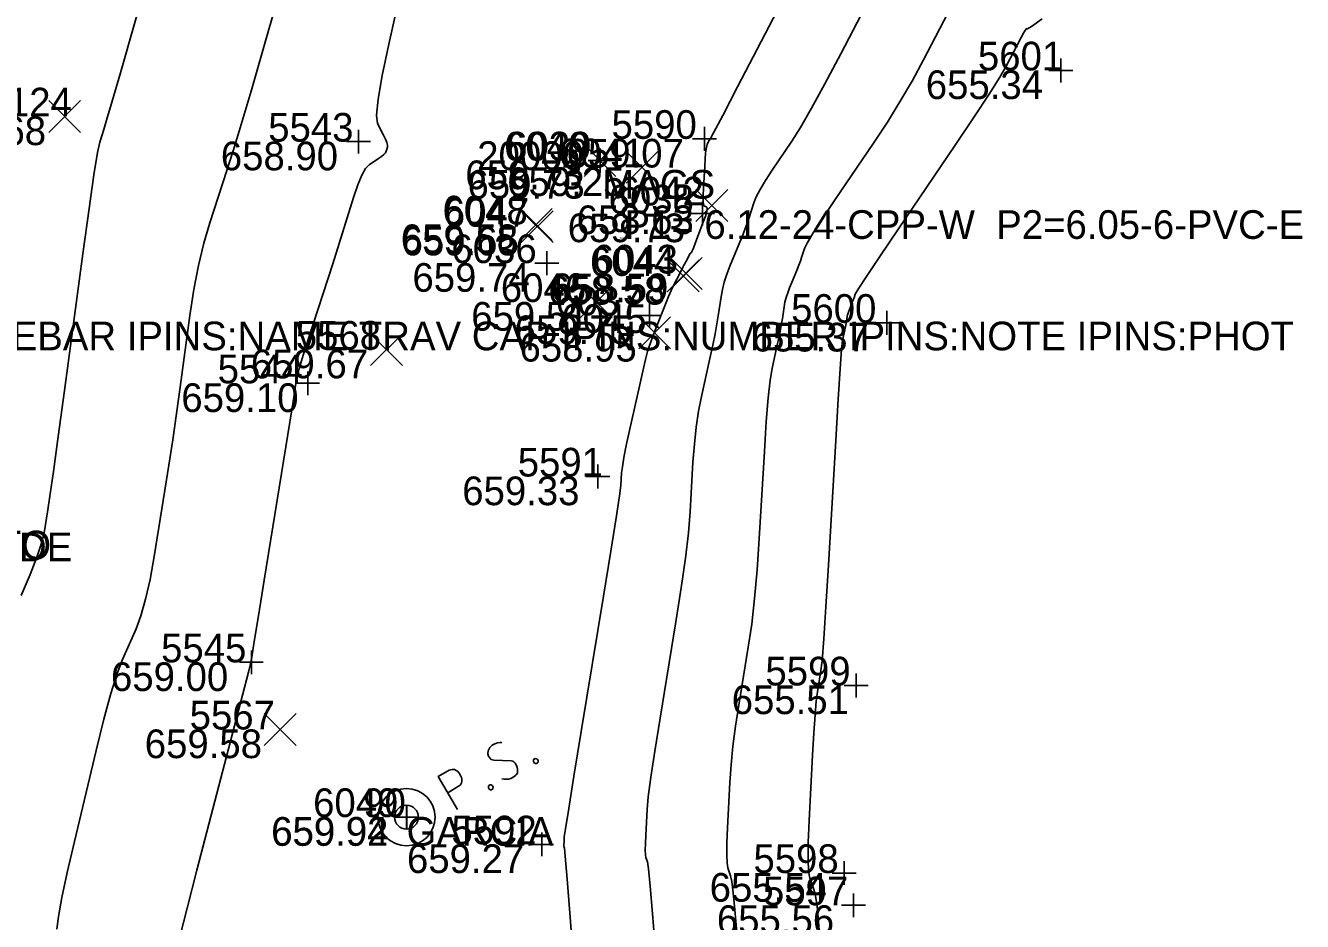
# Model space of a CAD drawing. Extents: x 2129350 to 2137777, y 657588 to 659885.
# Drawn here: x 2132984.1 to 2133037.5, y 658421.4 to 658458.9 of the extents above; entities that cross this region are included whole.
import ezdxf

# ---------------------------------------------------------------- set-up
doc = ezdxf.new("R2010")
doc.units = 0
for name, color, linetype in [('DT_X_Contour_Minor', 7, 'Continuous'), ('SV_P_Mon_Cells_Set', 7, 'Continuous'), ('SV_X_Random_Point', 7, 'Continuous'), ('SV_X_Shot_Marker', 7, 'Continuous'), ('SV_X_Text_Comment', 7, 'Continuous'), ('SV_X_Text_Description', 7, 'Continuous'), ('SV_X_Text_Elevation', 7, 'Continuous'), ('SV_X_Text_Name', 7, 'Continuous')]:
    doc.layers.add(name, color=color, linetype=linetype)

msp = doc.modelspace()

# ---------------------------------------------------------------- linework, layer by layer
at = {"layer": 'DT_X_Contour_Minor'}
for points in [[(2132989.848, 658463.205), (2132988.036, 658456.873), (2132987.693, 658455.686), (2132987.462, 658454.895), (2132987.342, 658454.5), (2132987.171, 658453.973), (2132987.078, 658453.532), (2132986.93, 658452.605), (2132986.725, 658451.191), (2132986.464, 658449.291), (2132985.693, 658443.576), (2132985.433, 658441.656), (2132985.23, 658440.183), (2132985.085, 658439.155), (2132984.998, 658438.574), (2132984.843, 658437.619), (2132984.74, 658437.186), (2132984.545, 658436.604), (2132984.259, 658435.873), (2132983.882, 658434.993)], [(2133017.349, 658462.959), (2133013.87, 658456.279), (2133013.249, 658455.089), (2133012.869, 658454.364), (2133012.728, 658454.102), (2133012.674, 658454.022), (2133012.655, 658453.99), (2133012.636, 658453.955), (2133012.62, 658453.915), (2133012.605, 658453.872), (2133012.566, 658453.752), (2133012.551, 658453.67), (2133012.534, 658453.511), (2133012.516, 658453.277), (2133012.497, 658452.967), (2133012.443, 658452.039), (2133012.43, 658451.732), (2133012.432, 658451.506), (2133012.449, 658451.363), (2133012.48, 658451.302), (2133012.584, 658451.248), (2133012.605, 658451.196), (2133012.59, 658451.08), (2133012.539, 658450.9), (2133012.452, 658450.657), (2133012.172, 658449.922), (2133012.079, 658449.68), (2133012.01, 658449.505), (2133011.964, 658449.398), (2133011.941, 658449.357), (2133011.913, 658449.339), (2133011.888, 658449.305), (2133011.836, 658449.213), (2133011.757, 658449.065), (2133011.65, 658448.861), (2133011.328, 658448.241), (2133011.209, 658448.005), (2133011.094, 658447.761), (2133010.984, 658447.511), (2133010.877, 658447.254), (2133010.598, 658446.557), (2133010.501, 658446.312), (2133010.417, 658446.099), (2133010.349, 658445.918), (2133010.294, 658445.769), (2133010.167, 658445.414), (2133010.106, 658445.21), (2133010.019, 658444.867), (2133009.904, 658444.382), (2133009.763, 658443.758), (2133009.351, 658441.905), (2133009.215, 658441.273), (2133009.114, 658440.766), (2133009.049, 658440.383), (2133009.02, 658440.125), (2133008.989, 658439.604), (2133008.935, 658439.168), (2133008.797, 658438.25), (2133008.573, 658436.849), (2133008.265, 658434.967), (2133007.33, 658429.306), (2133007.023, 658427.438), (2133006.802, 658426.079), (2133006.668, 658425.23), (2133006.62, 658424.89), (2133006.608, 658424.661), (2133006.605, 658424.585), (2133006.604, 658424.526), (2133006.606, 658424.484), (2133006.61, 658424.46), (2133006.624, 658424.42), (2133006.654, 658424.089), (2133006.733, 658423.125), (2133006.861, 658421.528), (2133007.038, 658419.298)], [(2133000.154, 658462.007), (2132999.27, 658458.075), (2132998.992, 658456.762), (2132998.821, 658455.771), (2132998.757, 658455.103), (2132998.8, 658454.757), (2132999.056, 658454.264), (2132999.138, 658454.095), (2132999.191, 658453.955), (2132999.216, 658453.846), (2132999.212, 658453.767), (2132999.162, 658453.597), (2132999.128, 658453.529), (2132999.062, 658453.454), (2132998.965, 658453.371), (2132998.836, 658453.28), (2132998.449, 658453.027), (2132998.299, 658452.87), (2132998.14, 658452.589), (2132997.97, 658452.182), (2132997.791, 658451.652), (2132996.93, 658448.884), (2132995.896, 658445.705), (2132995.7, 658445.096), (2132995.556, 658444.632), (2132995.464, 658444.312), (2132995.424, 658444.136), (2132995.387, 658443.862), (2132995.34, 658443.557), (2132995.227, 658442.848), (2132995.048, 658441.737), (2132994.06, 658435.642), (2132993.816, 658434.139), (2132993.641, 658433.065), (2132993.536, 658432.42), (2132993.501, 658432.204), (2132993.496, 658432.189), (2132993.49, 658432.165), (2132993.481, 658432.126), (2132993.468, 658432.072), (2132993.399, 658431.787), (2132991.243, 658423.501), (2132990.832, 658421.914), (2132990.522, 658420.702)], [(2133020.094, 658461.324), (2133018.192, 658457.67), (2133017.529, 658456.414), (2133016.967, 658455.386), (2133016.506, 658454.586), (2133016.145, 658454.015), (2133015.318, 658452.794), (2133015.038, 658452.365), (2133014.817, 658451.994), (2133014.655, 658451.681), (2133014.553, 658451.426), (2133014.359, 658450.821), (2133014.278, 658450.58), (2133014.179, 658450.311), (2133014.063, 658450.012), (2133013.93, 658449.685), (2133013.551, 658448.774), (2133013.421, 658448.438), (2133013.316, 658448.112), (2133013.236, 658447.798), (2133013.18, 658447.493), (2133013.064, 658446.696), (2133013.01, 658446.36), (2133012.933, 658445.951), (2133012.834, 658445.467), (2133012.713, 658444.911), (2133012.361, 658443.328), (2133012.24, 658442.711), (2133012.141, 658442.047), (2133012.063, 658441.335), (2133012.006, 658440.576), (2133011.885, 658438.49), (2133011.814, 658437.617), (2133011.692, 658436.56), (2133011.518, 658435.32), (2133011.293, 658433.897), (2133010.626, 658429.858), (2133010.405, 658428.482), (2133010.241, 658427.386), (2133010.134, 658426.569), (2133010.085, 658426.031), (2133010.029, 658424.967), (2133010.014, 658424.609), (2133010.011, 658424.334), (2133010.018, 658424.141), (2133010.037, 658424.029), (2133010.102, 658423.843), (2133010.142, 658423.556), (2133010.211, 658422.835), (2133010.309, 658421.681), (2133010.438, 658420.092)], [(2133022.84, 658459.689), (2133021.653, 658457.409), (2133021.188, 658456.55), (2133020.685, 658455.683), (2133020.143, 658454.809), (2133019.562, 658453.927), (2133017.963, 658451.566), (2133017.432, 658450.774), (2133017.04, 658450.168), (2133016.787, 658449.748), (2133016.673, 658449.515), (2133016.553, 658449.141), (2133016.502, 658448.991), (2133016.441, 658448.824), (2133016.369, 658448.64), (2133016.287, 658448.437), (2133016.053, 658447.873), (2133015.972, 658447.665), (2133015.907, 658447.463), (2133015.857, 658447.268), (2133015.823, 658447.08), (2133015.751, 658446.586), (2133015.717, 658446.378), (2133015.67, 658446.125), (2133015.609, 658445.826), (2133015.534, 658445.481), (2133015.316, 658444.501), (2133015.234, 658444.008), (2133015.153, 658443.265), (2133015.073, 658442.272), (2133014.993, 658441.028), (2133014.781, 658437.377), (2133014.692, 658436.065), (2133014.586, 658434.87), (2133014.463, 658433.79), (2133014.322, 658432.826), (2133013.923, 658430.409), (2133013.787, 658429.527), (2133013.68, 658428.693), (2133013.6, 658427.908), (2133013.549, 658427.172), (2133013.451, 658425.273), (2133013.424, 658424.634), (2133013.417, 658424.142), (2133013.431, 658423.797), (2133013.465, 658423.598), (2133013.581, 658423.265), (2133013.63, 658423.023), (2133013.689, 658422.545), (2133013.758, 658421.833), (2133013.838, 658420.886)], [(2132994.424, 658459.269), (2132994.148, 658458.348), (2132993.505, 658456.103), (2132993.261, 658455.264), (2132993.011, 658454.43), (2132992.754, 658453.603), (2132992.49, 658452.781), (2132991.78, 658450.598), (2132991.528, 658449.741), (2132991.305, 658448.808), (2132991.11, 658447.799), (2132990.944, 658446.714), (2132990.54, 658443.719), (2132990.387, 658442.607), (2132990.229, 658441.516), (2132990.067, 658440.446), (2132989.9, 658439.398), (2132989.452, 658436.63), (2132989.278, 658435.663), (2132989.093, 658434.835), (2132988.898, 658434.147), (2132988.691, 658433.598), (2132988.127, 658432.322), (2132987.899, 658431.725), (2132987.639, 658430.89), (2132987.346, 658429.818), (2132987.021, 658428.507), (2132986.111, 658424.696), (2132985.81, 658423.396), (2132985.587, 658422.351), (2132985.444, 658421.563), (2132985.379, 658421.032)], [(2133026.629, 658459.138), (2133026.172, 658458.816), (2133026.009, 658458.712), (2133025.97, 658458.725), (2133025.935, 658458.687), (2133025.859, 658458.563), (2133025.743, 658458.352), (2133025.586, 658458.055), (2133025.114, 658457.147), (2133024.847, 658456.685), (2133024.403, 658455.98), (2133023.78, 658455.032), (2133022.98, 658453.84), (2133020.607, 658450.338), (2133019.826, 658449.183), (2133019.264, 658448.342), (2133018.919, 658447.816), (2133018.793, 658447.604), (2133018.747, 658447.46), (2133018.727, 658447.403), (2133018.676, 658447.267), (2133018.644, 658447.189), (2133018.554, 658446.972), (2133018.523, 658446.892), (2133018.498, 658446.814), (2133018.479, 658446.739), (2133018.466, 658446.667), (2133018.438, 658446.477), (2133018.425, 658446.397), (2133018.407, 658446.299), (2133018.383, 658446.184), (2133018.354, 658446.051), (2133018.27, 658445.674), (2133018.229, 658445.305), (2133018.166, 658444.484), (2133018.083, 658443.208), (2133017.98, 658441.479), (2133017.676, 658436.263), (2133017.571, 658434.514), (2133017.481, 658433.18), (2133017.407, 658432.26), (2133017.35, 658431.755), (2133017.219, 658430.96), (2133017.169, 658430.571), (2133017.118, 658430), (2133017.067, 658429.247), (2133017.014, 658428.313), (2133016.872, 658425.578), (2133016.834, 658424.659), (2133016.824, 658423.95), (2133016.843, 658423.453), (2133016.892, 658423.168), (2133017.06, 658422.688), (2133017.118, 658422.49), (2133017.167, 658422.256), (2133017.207, 658421.986), (2133017.237, 658421.68), (2133017.306, 658420.817)]]:
    msp.add_lwpolyline(points, dxfattribs=at)
at = {"layer": 'SV_P_Mon_Cells_Set'}
for points in [[(2133004.004, 658428.832), (2133003.972, 658428.843), (2133003.931, 658428.848), (2133003.826, 658428.831), (2133003.708, 658428.792), (2133003.632, 658428.747), (2133003.604, 658428.731), (2133003.499, 658428.626), (2133003.432, 658428.5), (2133003.416, 658428.374), (2133003.448, 658428.275), (2133003.486, 658428.21), (2133003.555, 658428.134), (2133003.676, 658428.102), (2133004.39, 658428.08), (2133004.463, 658428.064), (2133004.507, 658428.032), (2133004.564, 658427.978), (2133004.602, 658427.912), (2133004.631, 658427.842), (2133004.647, 658427.792), (2133004.659, 658427.727), (2133004.666, 658427.672), (2133004.665, 658427.628), (2133004.656, 658427.579), (2133004.64, 658427.541), (2133004.615, 658427.497), (2133004.592, 658427.469), (2133004.513, 658427.408), (2133004.379, 658427.331), (2133004.281, 658427.303), (2133004.113, 658427.307), (2133003.999, 658427.328)], [(2133005.349, 658428.142), (2133005.396, 658428.17), (2133005.437, 658428.165), (2133005.491, 658428.138), (2133005.523, 658428.083), (2133005.52, 658428.023), (2133005.504, 658427.985), (2133005.456, 658427.957), (2133005.415, 658427.962), (2133005.361, 658427.989), (2133005.329, 658428.044), (2133005.333, 658428.104), (2133005.349, 658428.142)], [(2133002.15, 658426.034), (2133001.345, 658427.417), (2133001.803, 658427.683), (2133001.857, 658427.7), (2133001.936, 658427.717), (2133001.977, 658427.712), (2133002.019, 658427.707), (2133002.088, 658427.674), (2133002.149, 658427.637), (2133002.218, 658427.561), (2133002.294, 658427.43), (2133002.31, 658427.381), (2133002.329, 658427.304), (2133002.335, 658427.206), (2133002.316, 658427.151), (2133002.3, 658427.113), (2133002.265, 658427.063), (2133002.195, 658427.008), (2133001.738, 658426.742)], [(2133003.462, 658427.045), (2133003.509, 658427.073), (2133003.551, 658427.068), (2133003.605, 658427.041), (2133003.636, 658426.986), (2133003.633, 658426.926), (2133003.617, 658426.888), (2133003.57, 658426.86), (2133003.528, 658426.865), (2133003.474, 658426.892), (2133003.443, 658426.946), (2133003.446, 658427.007), (2133003.462, 658427.045)]]:
    msp.add_lwpolyline(points, dxfattribs=at)
for radius in [1.2, 0.5]:
    msp.add_circle((2133000.015, 658425.718), radius, dxfattribs=at)
at = {"layer": 'SV_X_Random_Point'}
for p, q in [((2132985.038, 658454.378), (2132986.372, 658455.713)), ((2132985.038, 658455.713), (2132986.372, 658454.378)), ((2133007.448, 658452.532), (2133008.782, 658453.867)), ((2133007.448, 658453.867), (2133008.782, 658452.532)), ((2133009.202, 658452.247), (2133010.536, 658453.581)), ((2133009.202, 658453.581), (2133010.536, 658452.247)), ((2133012.125, 658450.654), (2133013.459, 658451.988)), ((2133012.125, 658451.988), (2133013.459, 658450.654)), ((2133004.775, 658449.858), (2133006.109, 658451.193)), ((2133004.775, 658451.193), (2133006.109, 658449.858)), ((2133004.82, 658449.764), (2133006.154, 658451.098)), ((2133004.82, 658451.098), (2133006.154, 658449.764)), ((2133010.929, 658447.703), (2133012.263, 658449.039)), ((2133010.929, 658449.039), (2133012.263, 658447.703)), ((2133011.05, 658447.804), (2133012.384, 658449.139)), ((2133011.05, 658449.139), (2133012.384, 658447.804)), ((2133007.282, 658446.612), (2133008.616, 658447.948)), ((2133007.282, 658447.948), (2133008.616, 658446.612)), ((2133009.737, 658445.318), (2133011.071, 658446.654)), ((2133009.737, 658446.654), (2133011.071, 658445.318)), ((2132998.509, 658444.617), (2132999.843, 658445.953)), ((2132998.509, 658445.953), (2132999.843, 658444.617)), ((2132994.058, 658428.72), (2132995.392, 658430.054)), ((2132994.058, 658430.054), (2132995.392, 658428.72))]:
    msp.add_line(p, q, dxfattribs=at)
at = {"layer": 'SV_X_Shot_Marker'}
for p, q in [((2133027.401, 658457.474), (2133027.401, 658456.474)), ((2133026.901, 658456.974), (2133027.901, 658456.974)), ((2133027.401, 658456.974), (2133027.401, 658456.974)), ((2132998.004, 658454.492), (2132998.004, 658453.492)), ((2133012.489, 658454.608), (2133012.489, 658453.608)), ((2132997.504, 658453.992), (2132998.504, 658453.992)), ((2132998.004, 658453.992), (2132998.004, 658453.992)), ((2133011.989, 658454.108), (2133012.989, 658454.108)), ((2133012.489, 658454.108), (2133012.489, 658454.108)), ((2133008.116, 658453.704), (2133008.116, 658452.704)), ((2133007.616, 658453.204), (2133008.616, 658453.204)), ((2133008.116, 658453.204), (2133008.116, 658453.204)), ((2133012.404, 658451.484), (2133012.404, 658450.484)), ((2133011.904, 658450.984), (2133012.904, 658450.984)), ((2133012.404, 658450.984), (2133012.404, 658450.984)), ((2133005.892, 658449.408), (2133005.892, 658448.408)), ((2133005.392, 658448.908), (2133006.392, 658448.908)), ((2133005.892, 658448.908), (2133005.892, 658448.908)), ((2133010.18, 658447.217), (2133010.18, 658446.217)), ((2133020.12, 658446.908), (2133020.12, 658445.908)), ((2133009.68, 658446.717), (2133010.68, 658446.717)), ((2133010.18, 658446.717), (2133010.18, 658446.717)), ((2133019.62, 658446.408), (2133020.62, 658446.408)), ((2133020.12, 658446.408), (2133020.12, 658446.408)), ((2132995.877, 658444.376), (2132995.877, 658443.376)), ((2132995.377, 658443.876), (2132996.377, 658443.876)), ((2132995.877, 658443.876), (2132995.877, 658443.876)), ((2133008.025, 658440.475), (2133008.025, 658439.475)), ((2133007.525, 658439.975), (2133008.525, 658439.975)), ((2133008.025, 658439.975), (2133008.025, 658439.975)), ((2132993.52, 658432.698), (2132993.52, 658431.698)), ((2132993.02, 658432.198), (2132994.02, 658432.198)), ((2132993.52, 658432.198), (2132993.52, 658432.198)), ((2133018.834, 658431.73), (2133018.834, 658430.73)), ((2133018.334, 658431.23), (2133019.334, 658431.23)), ((2133018.834, 658431.23), (2133018.834, 658431.23)), ((2133000.015, 658426.218), (2133000.015, 658425.218)), ((2133000.025, 658426.222), (2133000.025, 658425.222)), ((2132999.515, 658425.718), (2133000.515, 658425.718)), ((2132999.525, 658425.722), (2133000.525, 658425.722)), ((2133000.015, 658425.718), (2133000.015, 658425.718)), ((2133000.025, 658425.722), (2133000.025, 658425.722)), ((2133005.674, 658425.078), (2133005.674, 658424.078)), ((2133005.174, 658424.578), (2133006.174, 658424.578)), ((2133005.674, 658424.578), (2133005.674, 658424.578)), ((2133018.335, 658423.879), (2133018.335, 658422.879)), ((2133017.835, 658423.379), (2133018.835, 658423.379)), ((2133018.335, 658423.379), (2133018.335, 658423.379)), ((2133018.723, 658422.527), (2133018.723, 658421.527)), ((2133018.223, 658422.027), (2133019.223, 658422.027)), ((2133018.723, 658422.027), (2133018.723, 658422.027))]:
    msp.add_line(p, q, dxfattribs=at)

# ---------------------------------------------------------------- texts
at = {"layer": 'SV_X_Text_Comment'}
for s, p in [('MAGS', (2133008.208, 658451.606)), ('IPINS:SIZE 5/8 REBAR IPINS:NAME TRAV CAP IPINS:NUMBER IPINS:NOTE IPINS:PHOT', (2132971.002, 658445.258)), ('T:TYPE MAPLE T:PHOTO', (2132966.055, 658436.508)), ('BLAZED TREE EAST SIDE', (2132966.226, 658436.426)), ('GARCIA', (2133000.015, 658424.518))]:
    msp.add_text(s, height=1.2, dxfattribs=at).set_placement(p)
at = {"layer": 'SV_X_Text_Description'}
msp.add_text('P1= 6.12-24-CPP-W  P2=6.05-6-PVC-E', height=1.2, dxfattribs=at).set_placement((2133009.137, 658449.921))
at = {"layer": 'SV_X_Text_Elevation'}
for s, height, p in [('655.34', 1.2, (2133021.751, 658455.774)), ('656.68', 1.2, (2132980.017, 658453.846)), ('658.90', 1.2, (2132992.241, 658452.792)), ('659.07', 1.2, (2133006.716, 658452.908)), ('659.73', 1.2, (2133002.474, 658452)), ('659.73', 1.2, (2133002.475, 658452.004)), ('659.73', 1.2, (2133002.567, 658451.606)), ('659.25', 1.2, (2133004.228, 658451.714)), ('658.63', 1.2, (2133007.133, 658450.121)), ('659.73', 1.2, (2133006.763, 658449.784)), ('659.58', 1.2, (2132999.773, 658449.326)), ('659.65', 1.2, (2132999.809, 658449.231)), ('659.71', 0.06, (2133008.878, 658449.861)), ('659.74', 1.2, (2133000.261, 658447.708)), ('658.59', 1.2, (2133006.067, 658447.272)), ('658.58', 1.2, (2133005.946, 658447.171)), ('659.51', 1.2, (2133002.723, 658446.08)), ('659.75', 1.2, (2133004.539, 658445.517)), ('655.37', 1.2, (2133014.461, 658445.208)), ('658.95', 1.2, (2133004.745, 658444.786)), ('659.67', 1.2, (2132993.498, 658444.085)), ('659.10', 1.2, (2132990.587, 658442.676)), ('659.33', 1.2, (2133002.347, 658438.775)), ('659.00', 1.2, (2132987.643, 658430.998)), ('655.51', 1.2, (2133013.627, 658430.03)), ('659.58', 1.2, (2132989.056, 658428.187)), ('659.92', 1.2, (2132994.346, 658424.518)), ('659.92', 1.2, (2132994.346, 658424.518)), ('659.94', 1.2, (2132994.356, 658424.522)), ('659.27', 1.2, (2133000.033, 658423.378)), ('655.54', 1.2, (2133012.704, 658422.179)), ('655.56', 1.2, (2133013.007, 658420.827))]:
    msp.add_text(s, height=height, dxfattribs=at).set_placement(p)
at = {"layer": 'SV_X_Text_Name'}
for s, height, p in [('5601', 1.2, (2133023.933, 658456.974)), ('5124', 1.2, (2132982.436, 658455.046)), ('5543', 1.2, (2132994.225, 658453.992)), ('5590', 1.2, (2133008.596, 658454.108)), ('6040', 1.2, (2133004.1, 658453.2)), ('6039', 1.2, (2133004.186, 658453.204)), ('20000', 1.2, (2133002.974, 658452.806)), ('6041', 1.2, (2133006.391, 658452.914)), ('6038', 1.2, (2133008.474, 658450.984)), ('6042', 1.2, (2133008.89, 658451.321)), ('6048', 1.2, (2133001.521, 658450.526)), ('6047', 1.2, (2133001.576, 658450.431)), ('6036', 1.2, (2133001.895, 658448.908)), ('6044', 1.2, (2133007.694, 658448.371)), ('6043', 1.2, (2133007.806, 658448.472)), ('5585', 0.06, (2133008.949, 658449.921)), ('6046', 1.2, (2133003.962, 658447.28)), ('6037', 1.2, (2133006.259, 658446.717)), ('5600', 1.2, (2133016.114, 658446.408)), ('6045', 1.2, (2133006.493, 658445.986)), ('5568', 1.2, (2132995.378, 658445.285)), ('5544', 1.2, (2132992.107, 658443.876)), ('5591', 1.2, (2133004.67, 658439.975)), ('5545', 1.2, (2132989.741, 658432.198)), ('5599', 1.2, (2133015.036, 658431.23)), ('5567', 1.2, (2132990.936, 658429.387)), ('6049', 1.2, (2132996.104, 658425.722)), ('90', 1.2, (2132998.201, 658425.718)), ('90', 1.2, (2132998.201, 658425.718)), ('5592', 1.2, (2133001.895, 658424.578)), ('5598', 1.2, (2133014.537, 658423.379)), ('5597', 1.2, (2133014.934, 658422.027))]:
    msp.add_text(s, height=height, dxfattribs=at).set_placement(p)

doc.saveas('drawing.dxf')
